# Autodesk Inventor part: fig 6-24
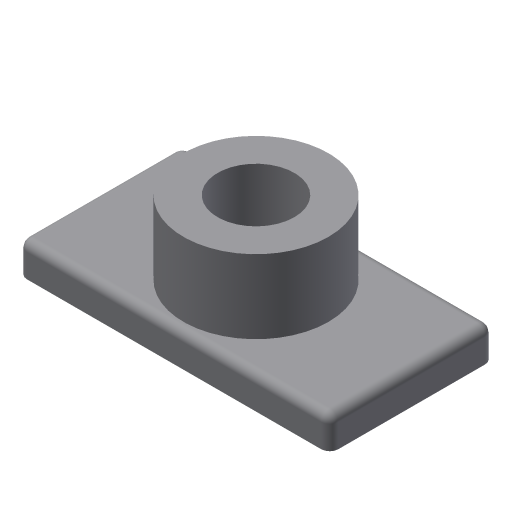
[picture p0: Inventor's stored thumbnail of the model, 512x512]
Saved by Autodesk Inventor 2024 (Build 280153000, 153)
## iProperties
Created: 2004-05
Part Number: fig 6-24
Document SubType Name: Modeling
Designer: CADCIM Technologies
Manufacturer: Standard
Standards Organization: Custom
Density: 1 g/cm^3
Material: Generic
Appearance: Default
Author: CADCIM Technologies
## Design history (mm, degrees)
sketch "Sketch1"
  geometry: L1 (-39.276, -18.692)-(33.721, -18.692); L2 (33.721, -18.692)-(33.721, 19.728); L3 (33.721, 19.728)-(-39.276, 19.728); L4 (-39.276, 19.728)-(-39.276, -18.692)
  constraints: 8 end point, 2 parallel, 1 horizontal, 1 perpendicular
extrude "Extrusion1" new body sketch "Sketch1" distance "d0" = 7.5; taper "d1" = 0 deg
sketch "Sketch2"
  geometry: C1 r 17 at (-2.778, 0.518)
  constraints: 1 centre point
  dimensions: "d16" = 34 diameter of C1
extrude "Extrusion2" join sketch "Sketch2" distance "d3" = 17.25; taper "d4" = 0 deg
hole "Hole1" diameter "d8" = 18; stored, may be unused: countersink angle "d12" = 90 deg, drill point angle "d14" = 118 deg; dims "d6" = 10, "d7" = 10, "d9" = 6, "d10" = 4, "d11" = 2, "d13" = 8
fillet "Fillet4" dims "d17" = 2
body "Solid1"
